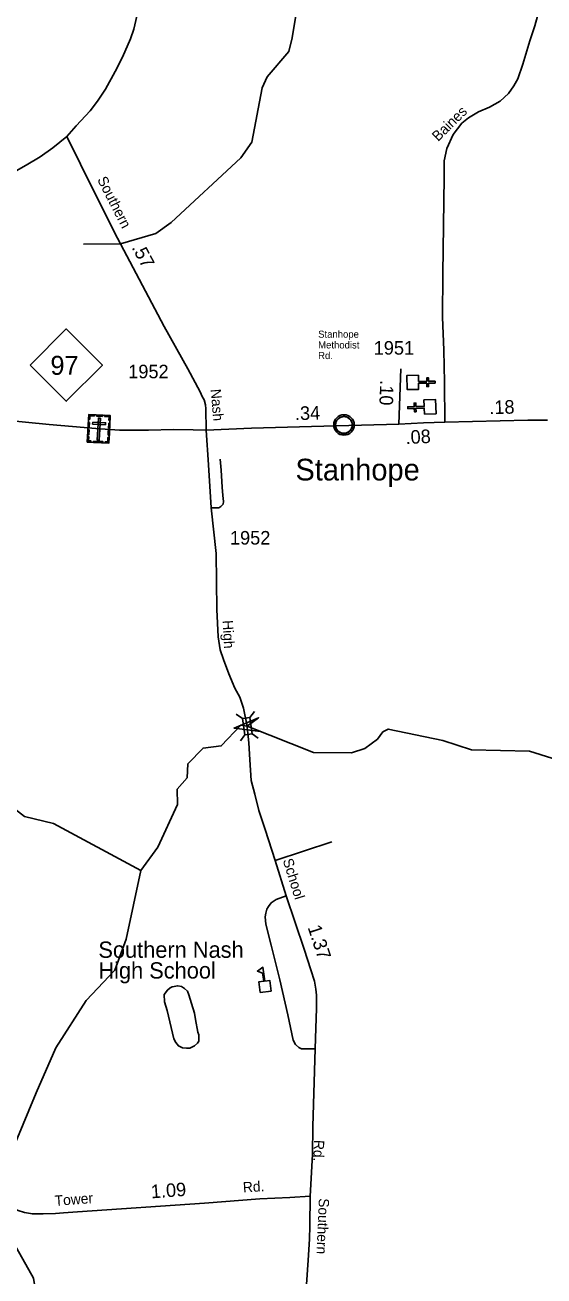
# Model space of a CAD drawing. Extents: x 2220236 to 2384410, y 720751 to 894131.
# Drawn here: x 2268254 to 2273033, y 763290 to 774823 of the extents above; entities that cross this region are included whole.
import ezdxf

# ---------------------------------------------------------------- set-up
doc = ezdxf.new("R2010")
doc.units = 0
for name, color, linetype in [('Exist Civil Demographics Community CELL', 7, 'Continuous'), ('Exist Civil Demographics Community Label', 7, 'Continuous'), ('Exist Cultural Cemetery CELL', 7, 'Continuous'), ('Exist Cultural Church CELL', 7, 'Continuous'), ('Exist Cultural Educational Facility Elementary CELL', 7, 'Continuous'), ('Exist Cultural Educational Facility Elementary Label', 7, 'Continuous'), ('Exist Hydrographic Creek Single Shore', 7, 'Continuous'), ('Exist Hydrographic Misc Water Feature', 7, 'Continuous'), ('Exist Road Non-System Type 51', 7, 'Continuous'), ('Exist Road Primary NC Attributed', 7, 'Continuous'), ('Exist Road Primary NC Service Mileage Hundredths English Label', 7, 'Continuous'), ('Exist Road Primary NC Shield CELL', 7, 'Continuous'), ('Exist Road Primary NC Shield Number Label', 7, 'Continuous'), ('Exist Road Secondary Mileage Hundredths English Label', 7, 'Continuous'), ('Exist Road Secondary Structure Standard Bridge Attributed CELL', 7, 'Continuous'), ('Exist Road Secondary Structure Standard Bridge CELL', 7, 'Continuous'), ('Exist Road Secondary Type 51 Attributed', 7, 'Continuous'), ('Exist Road Secondary Type 51 Label', 7, 'Continuous'), ('Exist Road Secondary Type 51 Number Label', 7, 'Continuous')]:
    doc.layers.add(name, color=color, linetype=linetype)

msp = doc.modelspace()

# ---------------------------------------------------------------- linework, layer by layer
at = {"layer": 'Exist Civil Demographics Community CELL'}
msp.add_lwpolyline([(2271113, 771148), (2271114, 771154), (2271116, 771160), (2271119, 771167), (2271122, 771173), (2271125, 771179), (2271129, 771184), (2271133, 771188), (2271137, 771193), (2271143, 771197), (2271148, 771201), (2271153, 771204), (2271158, 771206), (2271164, 771209), (2271169, 771211), (2271174, 771212), (2271179, 771212), (2271183, 771213), (2271189, 771213), (2271193, 771213), (2271199, 771213), (2271204, 771212), (2271209, 771211), (2271214, 771210), (2271219, 771208), (2271226, 771205), (2271232, 771202), (2271237, 771198), (2271242, 771194), (2271246, 771191), (2271250, 771187), (2271254, 771182), (2271257, 771177), (2271260, 771172), (2271262, 771167), (2271264, 771162), (2271266, 771157), (2271267, 771152), (2271268, 771146), (2271269, 771142), (2271269, 771136), (2271269, 771130), (2271268, 771124), (2271267, 771119), (2271266, 771113), (2271264, 771107), (2271262, 771102), (2271258, 771096), (2271255, 771090), (2271252, 771086), (2271247, 771081), (2271242, 771076), (2271237, 771072), (2271232, 771068), (2271228, 771066), (2271221, 771063), (2271214, 771060), (2271208, 771058), (2271201, 771057), (2271197, 771057), (2271192, 771056), (2271187, 771056), (2271182, 771057), (2271177, 771058), (2271171, 771059), (2271166, 771060), (2271161, 771062), (2271157, 771064), (2271153, 771066), (2271146, 771070), (2271140, 771075), (2271135, 771079), (2271131, 771084), (2271128, 771088), (2271125, 771092), (2271121, 771099), (2271119, 771103), (2271117, 771107), (2271115, 771115), (2271113, 771122), (2271112, 771127), (2271112, 771134), (2271112, 771138), (2271113, 771145)], close=True, dxfattribs=at)
for centre, radius in [((2271191, 771136), 94.3), ((2271190, 771136), 76.7)]:
    msp.add_circle(centre, radius, dxfattribs=at)
at = {"layer": 'Exist Cultural Cemetery CELL'}
for points in [[(2268840, 771232), (2269039, 771222), (2269026, 770968), (2268827, 770978)], [(2268838, 771189), (2268849, 771189), (2268851, 771221), (2268891, 771219), (2268892, 771230), (2268840, 771232)], [(2268834, 771115), (2268836, 771158), (2268847, 771158), (2268845, 771115)], [(2268877, 771162), (2268876, 771144), (2268994, 771138), (2268995, 771156)], [(2268914, 771229), (2268966, 771226), (2268965, 771215), (2268913, 771217)], [(2268947, 771198), (2268929, 771199), (2268918, 770996), (2268937, 770995)], [(2269037, 771179), (2269025, 771180), (2269027, 771212), (2268986, 771214), (2268987, 771225), (2269039, 771222)], [(2269021, 771107), (2269024, 771150), (2269035, 771149), (2269033, 771106)], [(2268860, 770976), (2268861, 770988), (2268839, 770989), (2268841, 771029), (2268830, 771030), (2268827, 770978)], [(2268831, 771048), (2268833, 771091), (2268844, 771091), (2268842, 771047)], [(2268993, 770970), (2268993, 770981), (2269015, 770980), (2269017, 771021), (2269028, 771020), (2269026, 770968)], [(2269018, 771041), (2269020, 771084), (2269032, 771084), (2269030, 771040)], [(2268885, 770987), (2268970, 770982), (2268969, 770971), (2268884, 770975)]]:
    msp.add_lwpolyline(points, close=True, dxfattribs=at)
at = {"layer": 'Exist Cultural Church CELL'}
for points in [[(2271877, 771594), (2271878, 771537), (2271954, 771537), (2271954, 771569), (2271970, 771570), (2271970, 771538), (2272030, 771538), (2272030, 771522), (2271970, 771522), (2271970, 771490), (2271954, 771489), (2271954, 771521), (2271878, 771521), (2271878, 771463), (2271772, 771463), (2271771, 771593)], [(2271933, 771235), (2271931, 771292), (2271854, 771290), (2271855, 771258), (2271840, 771257), (2271838, 771289), (2271778, 771287), (2271778, 771303), (2271838, 771305), (2271837, 771337), (2271853, 771338), (2271854, 771306), (2271930, 771308), (2271928, 771366), (2272035, 771369), (2272039, 771239)]]:
    msp.add_lwpolyline(points, close=True, dxfattribs=at)
at = {"layer": 'Exist Cultural Educational Facility Elementary CELL'}
msp.add_lwpolyline([(2270418, 765904), (2270406, 766001), (2270452, 766007), (2270442, 766082), (2270393, 766100), (2270445, 766136), (2270461, 766008), (2270507, 766014), (2270519, 765917)], close=True, dxfattribs=at)
at = {"layer": 'Exist Hydrographic Creek Single Shore'}
for points in [[(2273469, 767949), (2272901, 768128), (2272367, 768139), (2272100, 768226), (2271599, 768332), (2271549, 768307), (2271500, 768239), (2271384, 768153), (2271260, 768113), (2270910, 768116), (2270300, 768358), (2270240, 768368), (2270060, 768177), (2269893, 768157), (2269753, 768012), (2269746, 767881), (2269655, 767778), (2269657, 767637), (2269477, 767244), (2269321, 767028)], [(2269321, 767028), (2268517, 767461), (2268250, 767525), (2268040, 767690), (2267757, 767719), (2267439, 767860), (2267422, 767900)], [(2267252, 759353), (2267385, 759429), (2267773, 759775), (2268076, 760375), (2268437, 760922), (2268567, 761274), (2268613, 761630), (2268594, 761939), (2268405, 762553), (2268393, 762894), (2268332, 763269), (2268094, 763691), (2268058, 763921), (2268058, 763953), (2268061, 764085), (2268074, 764141), (2268170, 764526), (2268357, 764978), (2268537, 765394), (2268816, 765831), (2269080, 766108), (2269185, 766394), (2269321, 767028)]]:
    msp.add_lwpolyline(points, dxfattribs=at)
at = {"layer": 'Exist Hydrographic Misc Water Feature'}
for points in [[(2270714, 774706), (2270760, 774984), (2270742, 775152), (2270725, 775192), (2270723, 775369), (2270748, 775401), (2270733, 776077), (2270758, 776142), (2270865, 776219), (2270856, 776327), (2270822, 776384), (2270820, 776600), (2270885, 776802), (2270992, 776921), (2271274, 777073), (2271304, 777215)], [(2268792, 772804), (2269134, 772807), (2269457, 772902), (2269598, 773001), (2270242, 773598), (2270341, 773743), (2270436, 774243), (2270485, 774344), (2270683, 774579), (2270713, 774704)], [(2270713, 774704), (2270714, 774706)]]:
    msp.add_lwpolyline(points, dxfattribs=at)
at = {"layer": 'Exist Road Non-System Type 51'}
msp.add_line((2271079, 767293), (2270558, 767120), dxfattribs=at)
for points in [[(2270051, 770820), (2270060, 770718), (2270070, 770563), (2270075, 770485), (2270080, 770431), (2270078, 770405), (2270057, 770384), (2270037, 770372), (2269969, 770371)], [(2270660, 766796), (2270565, 766760), (2270521, 766731), (2270495, 766697), (2270480, 766672), (2270470, 766635), (2270464, 766601), (2270472, 766534), (2270521, 766340), (2270599, 766021), (2270675, 765698), (2270724, 765465), (2270745, 765424), (2270776, 765397), (2270799, 765384), (2270927, 765384)], [(2269813, 765712), (2269825, 765655), (2269846, 765539), (2269855, 765513), (2269853, 765455), (2269841, 765435), (2269815, 765413), (2269770, 765390), (2269740, 765390), (2269704, 765394), (2269666, 765411), (2269641, 765443), (2269623, 765475), (2269561, 765738), (2269538, 765816), (2269535, 765886), (2269565, 765926), (2269589, 765946), (2269609, 765956), (2269660, 765965), (2269696, 765959), (2269723, 765941), (2269751, 765916), (2269763, 765882), (2269788, 765802), (2269813, 765712)]]:
    msp.add_lwpolyline(points, dxfattribs=at)
at = {"layer": 'Exist Road Primary NC Attributed'}
for points in [[(2268638, 773795), (2268724, 773892), (2268853, 774031), (2268921, 774120), (2268994, 774232), (2269085, 774395), (2269151, 774527), (2269224, 774695), (2269255, 774784), (2269292, 774944), (2269339, 775182), (2269359, 775350), (2269382, 775467), (2269397, 775606), (2269429, 775824), (2269452, 775946), (2269478, 776117), (2269519, 776376), (2269733, 777203)], [(2266561, 771421), (2266550, 771537), (2266528, 771715), (2266541, 771893), (2266558, 772037), (2266594, 772174), (2266631, 772291), (2266670, 772381), (2266796, 772561), (2266902, 772702), (2266977, 772784), (2267038, 772833), (2267150, 772914), (2267297, 773006), (2267480, 773111), (2267689, 773219), (2267924, 773338), (2268107, 773443), (2268263, 773531), (2268392, 773607), (2268511, 773690), (2268638, 773795)], [(2266561, 771421), (2266705, 771396), (2266877, 771356), (2267531, 771234), (2267746, 771203), (2268041, 771183), (2268477, 771139), (2268904, 771102), (2269124, 771088), (2269392, 771088), (2269621, 771093), (2269802, 771090), (2269921, 771089)], [(2269921, 771089), (2270340, 771107), (2270891, 771121), (2271696, 771144)], [(2271696, 771144), (2271924, 771155), (2272121, 771162)], [(2272121, 771162), (2272885, 771181), (2273066, 771180)]]:
    msp.add_lwpolyline(points, dxfattribs=at)
at = {"layer": 'Exist Road Primary NC Shield CELL'}
msp.add_lwpolyline([(2268300, 771688), (2268633, 772021), (2268966, 771688), (2268633, 771355)], close=True, dxfattribs=at)
at = {"layer": 'Exist Road Secondary Structure Standard Bridge Attributed CELL'}
msp.add_lwpolyline([(2270421, 768311), (2270179, 768341), (2270404, 768436), (2270300, 768358)], close=True, dxfattribs=at)
at = {"layer": 'Exist Road Secondary Structure Standard Bridge CELL'}
for p, q in [((2270199, 768470), (2270255, 768428)), ((2270366, 768494), (2270325, 768439)), ((2270278, 768279), (2270237, 768224)), ((2270346, 768289), (2270401, 768248))]:
    msp.add_line(p, q, dxfattribs=at)
msp.add_lwpolyline([(2270325, 768439), (2270346, 768289), (2270277, 768279), (2270255, 768428)], close=True, dxfattribs=at)
at = {"layer": 'Exist Road Secondary Type 51 Attributed'}
msp.add_line((2271696, 771144), (2271714, 771653), dxfattribs=at)
for points in [[(2273043, 775290), (2272972, 774905), (2272949, 774814), (2272902, 774677), (2272838, 774462), (2272791, 774327), (2272755, 774263), (2272705, 774192), (2272628, 774122), (2272532, 774065), (2272430, 774024), (2272339, 773967), (2272277, 773917), (2272197, 773813), (2272137, 773686), (2272114, 773572), (2272113, 773420), (2272101, 772529), (2272099, 772129), (2272110, 771824), (2272118, 771530), (2272121, 771162)], [(2268638, 773795), (2268890, 773285), (2269104, 772857), (2269536, 772045), (2269753, 771652), (2269865, 771442), (2269885, 771398), (2269902, 771368), (2269916, 771322), (2269920, 771283), (2269921, 771089)], [(2269921, 771089), (2269942, 770768), (2269969, 770371), (2270015, 769950), (2270021, 769435), (2270033, 769183), (2270051, 769063), (2270080, 768973), (2270132, 768840), (2270187, 768708), (2270233, 768627), (2270267, 768524), (2270295, 768373), (2270306, 768293)], [(2270306, 768293), (2270316, 768205), (2270325, 768047), (2270335, 767859), (2270371, 767732), (2270407, 767580), (2270464, 767406), (2270558, 767120), (2270660, 766796), (2270823, 766303), (2270886, 766113), (2270919, 766007), (2270932, 765934), (2270937, 765878), (2270939, 765756), (2270932, 765574), (2270927, 765384), (2270904, 764668), (2270901, 764411), (2270880, 764025)], [(2268056, 763959), (2268106, 763930), (2268189, 763893), (2268247, 763875), (2268322, 763862), (2268420, 763864), (2268533, 763867), (2268607, 763872), (2268738, 763880), (2269906, 763961), (2270415, 764000), (2270691, 764012), (2270880, 764025)], [(2270880, 764025), (2270875, 763751), (2270872, 763630), (2270862, 763436), (2270847, 763212)]]:
    msp.add_lwpolyline(points, dxfattribs=at)

# ---------------------------------------------------------------- texts
at = {"layer": 'Exist Civil Demographics Community Label'}
msp.add_text('Stanhope', height=200, dxfattribs=at).set_placement((2270744, 770624))
at = {"layer": 'Exist Cultural Educational Facility Elementary Label'}
for s, p in [('Southern Nash', (2268929, 766223)), ('High School', (2268929, 766032))]:
    msp.add_text(s, height=150, dxfattribs=at).set_placement(p)
at = {"layer": 'Exist Road Primary NC Service Mileage Hundredths English Label'}
for s, rotation, p in [('.18', 1.4635, (2272531, 771235)), ('.34', 1.5217, (2270741, 771180)), ('.08', 2.8644, (2271761, 770959))]:
    msp.add_text(s, height=125, rotation=rotation, dxfattribs=at).set_placement(p)
at = {"layer": 'Exist Road Primary NC Shield Number Label'}
msp.add_text('97', height=175, dxfattribs=at).set_placement((2268487, 771598))
at = {"layer": 'Exist Road Secondary Mileage Hundredths English Label'}
for s, rotation, p in [('.57', 298.1143, (2269233, 772772)), ('.10', 267.9885, (2271525, 771550)), ('1.37', 288.2161, (2270855, 766504)), ('1.09', 4.1051, (2269417, 764005))]:
    msp.add_text(s, height=125, rotation=rotation, dxfattribs=at).set_placement(p)
at = {"layer": 'Exist Road Secondary Type 51 Label'}
for s, height, rotation, p in [('Baines', 95, 44.7931, (2272058, 773744)), ('Southern', 95, 296.9655, (2268916, 773398)), ('Stanhope', 65.6, 360, (2270953, 771940)), ('Methodist', 65.6, 360, (2270953, 771841)), ('Rd.', 65.6, 360, (2270953, 771743)), ('Nash', 95, 274.7578, (2269963, 771464)), ('High', 95, 273.1925, (2270073, 769333)), ('School', 95, 287.2441, (2270626, 767123)), ('Rd.', 95, 268.0445, (2270915, 764545)), ('Rd.', 95, 3.7419, (2270263, 764059)), ('Tower', 95, 4.1494, (2268530, 763936)), ('Southern', 95, 267.602, (2270960, 764008))]:
    msp.add_text(s, height=height, rotation=rotation, dxfattribs=at).set_placement(p)
at = {"layer": 'Exist Road Secondary Type 51 Number Label'}
for s, p in [('1951', (2271465, 771784)), ('1952', (2269204, 771566)), ('1952', (2270141, 770033))]:
    msp.add_text(s, height=125, dxfattribs=at).set_placement(p)

doc.saveas('drawing.dxf')
